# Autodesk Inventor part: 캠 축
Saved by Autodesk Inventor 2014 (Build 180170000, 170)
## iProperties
Created: 2026-06
Part Number: 캠 축
Material: 일반
Document SubType Name: Modeling
Designer: dg
Density: 1 g/cm^3
Appearance: 기본값
Author: dg
Author: jhkim
Creation Date: 2026-05-29
Sending System: Autodesk Inventor 2027
Preprocessor: ST-DEVELOPER v20.1
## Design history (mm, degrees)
node "캠 축1"
node "솔리드1"
node "기준1"
